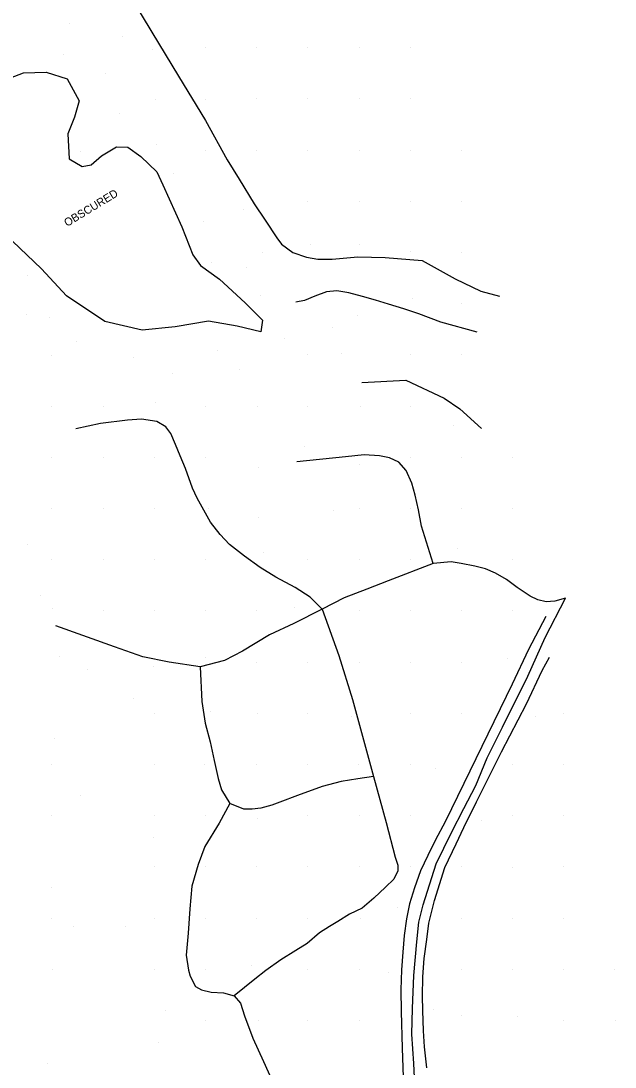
# Model space of a CAD drawing. Extents: x 524772 to 528246, y 273285 to 283088.
# Drawn here: x 527849.8 to 527963, y 274321.4 to 274520.7 of the extents above; entities that cross this region are included whole.
import ezdxf

# ---------------------------------------------------------------- set-up
doc = ezdxf.new("R2010")
doc.units = 0
for name, color, linetype in [('PH Exist DTM Breakline', 7, 'Continuous'), ('PH Exist DTM Obscure Area', 7, 'Continuous'), ('PH Exist DTM Obscure Area Text', 7, 'Continuous'), ('PH Exist DTM Point', 7, 'Continuous')]:
    doc.layers.add(name, color=color, linetype=linetype)

msp = doc.modelspace()

# ---------------------------------------------------------------- linework, layer by layer
at = {"layer": 'PH Exist DTM Breakline'}
for points in [[(527866.42, 274533.52), (527867.96, 274529.7), (527870.63, 274525.31), (527874.74, 274518.54), (527879.81, 274510.15), (527884.93, 274501.67), (527889.06, 274494.22), (527891.36, 274490.53), (527894.19, 274485.84), (527896.28, 274482.72), (527898.51, 274479.34), (527899.44, 274478.1), (527901.55, 274476.56), (527904.17, 274475.63), (527906.35, 274475.26), (527909.05, 274475.26), (527913.94, 274475.69), (527919.19, 274475.61), (527926.24, 274475.02), (527932.52, 274471.5), (527937.39, 274469.18), (527940.93, 274468.23)], [(527936.68, 274461.4), (527929.79, 274463.25), (527925.57, 274464.83), (527922.73, 274465.82), (527919.84, 274466.71), (527917.33, 274467.47), (527914.85, 274468.15), (527912.22, 274468.84), (527909.97, 274469.26), (527907.98, 274469.08), (527905.8, 274468.25), (527903.79, 274467.43), (527902.16, 274467.06)], [(527914.74, 274451.79), (527923.13, 274452.23), (527930.4, 274448.79), (527933.41, 274446.76), (527937.55, 274443.01)], [(527907.18, 274408.58), (527904.86, 274410.9), (527902.03, 274412.71), (527898.36, 274414.72), (527895.38, 274416.55), (527892.39, 274418.7), (527889.52, 274420.9), (527887.73, 274422.82), (527885.89, 274425.18), (527883.37, 274429.73), (527882.47, 274431.65), (527881.1, 274435.38), (527880.11, 274437.84), (527879.25, 274439.97), (527878.31, 274442.05), (527877.4, 274443.36), (527875.64, 274444.33), (527872.75, 274444.77), (527870.05, 274444.62), (527864.96, 274443.97), (527860.26, 274442.94)], [(527953.56, 274410.73), (527951.48, 274410.13), (527949.87, 274410.02), (527948.24, 274410.38), (527946.8, 274411.08), (527944.31, 274412.76), (527942.32, 274414.24), (527940.2, 274415.45), (527938.29, 274416.26), (527936.26, 274416.81), (527933.63, 274417.32), (527931.72, 274417.62), (527928.32, 274417.29), (527927.38, 274420.35), (527926.12, 274424.4), (527925.53, 274427.5), (527924.89, 274430.3), (527924.27, 274432.6), (527923.17, 274435.01), (527921.78, 274436.6), (527920, 274437.43), (527918.09, 274437.78), (527915.18, 274438.02), (527911.64, 274437.65), (527902.35, 274436.69)], [(527928.32, 274417.29), (527919.75, 274414.02), (527915.65, 274412.4), (527911.39, 274410.75), (527907.18, 274408.58), (527901.78, 274405.87), (527897.16, 274403.69), (527891.97, 274400.58), (527888.57, 274398.83), (527883.91, 274397.63), (527878.01, 274398.52), (527873.02, 274399.54), (527867.63, 274401.41), (527856.42, 274405.44)], [(527927.25, 274297.18), (527926.29, 274302.85), (527925.36, 274310.41), (527924.96, 274315.41), (527924.61, 274322.08), (527924.26, 274327.66), (527924.37, 274332.53), (527924.62, 274338.8), (527925.19, 274345.24), (527925.6, 274349.01), (527926.4, 274352.31), (527928.88, 274360.09), (527931.82, 274366.05), (527934.16, 274370.63), (527936.44, 274375.02), (527938.64, 274380.3), (527941.55, 274386.14), (527946.38, 274395.87), (527949.68, 274403.18), (527953.56, 274410.73)], [(527907.18, 274408.58), (527910.35, 274399.78), (527912.95, 274391.37), (527916.95, 274376.73), (527913.94, 274376.27), (527910.77, 274375.77), (527907.18, 274374.82), (527902.46, 274373.1), (527899.12, 274371.84), (527897.58, 274371.27), (527895.49, 274370.69), (527893.82, 274370.5), (527892.22, 274370.48), (527889.59, 274371.58)], [(527949.8, 274407.2), (527946.51, 274400.93), (527943.36, 274394.33), (527930.65, 274368.25), (527928.73, 274364.52), (527927.31, 274361.68), (527925.91, 274358.75), (527924.74, 274355.49), (527923.84, 274352.48), (527923.24, 274349.61), (527922.8, 274346.43), (527922.51, 274343.27), (527922.27, 274339.87), (527922.18, 274336.1), (527922.24, 274331.94), (527922.39, 274325), (527922.64, 274317.63), (527923.04, 274313.7), (527923.12, 274310.68), (527923.31, 274307.7), (527923.66, 274305), (527924.33, 274301.73), (527924.75, 274299.14), (527925.3, 274296.8)], [(527927.09, 274321.26), (527926.68, 274325.24), (527926.47, 274328.28), (527926.37, 274332.16), (527926.3, 274334.87), (527926.33, 274338.59), (527926.63, 274342.06), (527927.09, 274345.67), (527927.52, 274348.76), (527928.6, 274353.1), (527930.55, 274359.39), (527932.7, 274363.9), (527934.15, 274367.03), (527936.56, 274371.89), (527938.81, 274376.33), (527941.34, 274381.41), (527946.13, 274390.55), (527949.11, 274396.95), (527950.49, 274399.44)], [(527883.91, 274397.63), (527884.24, 274391.04), (527884.89, 274386.86), (527885.81, 274383.31), (527886.57, 274379.75), (527887.36, 274376.36), (527888.02, 274374.21), (527889.59, 274371.58), (527887.55, 274367.84), (527884.84, 274363.37), (527883.52, 274359.94), (527882.34, 274355.86), (527881.96, 274351.51), (527881.61, 274346.88), (527881.24, 274342.71), (527881.67, 274339.81), (527882.01, 274338.69), (527883.01, 274336.7), (527884.18, 274336.08), (527886.01, 274335.67), (527888.35, 274335.51), (527890.41, 274334.97), (527891.59, 274333.58), (527892.4, 274331.15), (527893.98, 274326.87), (527896.02, 274322.44), (527897.44, 274319.19)], [(527916.95, 274376.73), (527919.38, 274367.94), (527921.09, 274361.35), (527921.56, 274359.84), (527921.58, 274358.77), (527920.84, 274357.17), (527919.22, 274355.63), (527917.03, 274353.54), (527914.77, 274351.67), (527912.39, 274350.48), (527910.18, 274349.11), (527908.58, 274348.18), (527906.66, 274346.94), (527904.34, 274344.9), (527902.18, 274343.58), (527899.32, 274341.81), (527896.46, 274339.79), (527894.35, 274338.15), (527890.41, 274334.97)]]:
    msp.add_lwpolyline(points, dxfattribs=at)
at = {"layer": 'PH Exist DTM Obscure Area'}
for points in [[(527844.92, 274508.75), (527850.23, 274510.76), (527854.56, 274510.87), (527858.56, 274509.6), (527860.88, 274505.42), (527859.99, 274502.34), (527858.73, 274499.16), (527858.97, 274494.38), (527861.41, 274492.91), (527863.17, 274493.25), (527865.11, 274494.94), (527868, 274496.66), (527870.11, 274496.62), (527872.64, 274494.84), (527875.66, 274491.91), (527876.78, 274489.41)], [(527876.78, 274489.41), (527880.45, 274481.43), (527882.53, 274476.13), (527884.01, 274474.06), (527887.59, 274471.45), (527892.5, 274466.98), (527895.8, 274463.65), (527895.46, 274461.45), (527890.97, 274462.5), (527885.53, 274463.44), (527879.13, 274462.41), (527872.87, 274461.74), (527865.77, 274463.41), (527858.48, 274468.26), (527853.69, 274473.42), (527848.15, 274478.69)]]:
    msp.add_lwpolyline(points, dxfattribs=at)
at = {"layer": 'PH Exist DTM Point'}
for p, q in [((527859, 274520.18), (527859, 274520.18)), ((527869.07, 274517.69), (527869.07, 274517.69)), ((527874.77, 274515.15), (527874.77, 274515.15)), ((527884.93, 274515.57), (527884.93, 274515.57)), ((527894.71, 274515.56), (527894.71, 274515.56)), ((527904.46, 274515.56), (527904.46, 274515.56)), ((527914.2, 274515.53), (527914.2, 274515.53)), ((527923.97, 274515.56), (527923.97, 274515.56)), ((527857.87, 274514.24), (527857.87, 274514.24)), ((527865.95, 274510.71), (527865.95, 274510.71)), ((527875.33, 274505.76), (527875.33, 274505.76)), ((527885.02, 274505.78), (527885.02, 274505.78)), ((527894.71, 274505.8), (527894.71, 274505.8)), ((527904.46, 274505.8), (527904.46, 274505.8)), ((527914.19, 274505.81), (527914.19, 274505.81)), ((527923.97, 274505.8), (527923.97, 274505.8)), ((527868.56, 274503.05), (527868.56, 274503.05)), ((527875.63, 274497.06), (527875.63, 274497.06)), ((527861.15, 274495.79), (527861.15, 274495.79)), ((527884.87, 274496.06), (527884.87, 274496.06)), ((527894.71, 274496.05), (527894.71, 274496.05)), ((527904.44, 274496.06), (527904.44, 274496.06)), ((527914.22, 274496.05), (527914.22, 274496.05)), ((527923.97, 274496.05), (527923.97, 274496.05)), ((527933.74, 274496.05), (527933.74, 274496.05)), ((527878.8, 274491.57), (527878.8, 274491.57)), ((527904.46, 274486.29), (527904.46, 274486.29)), ((527914.22, 274486.29), (527914.22, 274486.29)), ((527923.97, 274486.29), (527923.97, 274486.29)), ((527933.72, 274486.29), (527933.72, 274486.29)), ((527892.26, 274484.64), (527892.26, 274484.64)), ((527884.48, 274482.46), (527884.48, 274482.46)), ((527904.95, 274478.13), (527904.95, 274478.13)), ((527914.36, 274478.08), (527914.36, 274478.08)), ((527895.87, 274476.51), (527895.87, 274476.51)), ((527924.08, 274476.65), (527924.08, 274476.65)), ((527933.72, 274476.54), (527933.72, 274476.54)), ((527886.04, 274474.6), (527886.04, 274474.6)), ((527892.69, 274473.76), (527892.69, 274473.76)), ((527851.05, 274472.09), (527851.05, 274472.09)), ((527895.43, 274468.3), (527895.43, 274468.3)), ((527924.43, 274467.79), (527924.43, 274467.79)), ((527933.72, 274466.79), (527933.72, 274466.79)), ((527850.77, 274464.74), (527850.77, 274464.74)), ((527855.15, 274464.23), (527855.15, 274464.23)), ((527913.85, 274464.61), (527913.85, 274464.61)), ((527909.08, 274462.24), (527909.08, 274462.24)), ((527860.43, 274459.53), (527860.43, 274459.53)), ((527900.01, 274460.18), (527900.01, 274460.18)), ((527887.2, 274457.88), (527887.2, 274457.88)), ((527910.84, 274457.21), (527910.84, 274457.21)), ((527855.69, 274456.99), (527855.69, 274456.99)), ((527871.29, 274456.63), (527871.29, 274456.63)), ((527904.46, 274457.03), (527904.46, 274457.03)), ((527923.97, 274457.03), (527923.97, 274457.03)), ((527933.72, 274457.03), (527933.72, 274457.03)), ((527878.74, 274453.4), (527878.74, 274453.4)), ((527891.47, 274454.33), (527891.47, 274454.33)), ((527855.69, 274447.28), (527855.69, 274447.28)), ((527865.46, 274447.3), (527865.46, 274447.3)), ((527875.45, 274448.04), (527875.45, 274448.04)), ((527884.95, 274447.28), (527884.95, 274447.28)), ((527894.94, 274447.25), (527894.94, 274447.25)), ((527904.46, 274447.28), (527904.46, 274447.28)), ((527923.97, 274447.28), (527923.97, 274447.28)), ((527914.48, 274447.2), (527914.48, 274447.2)), ((527932.11, 274443.61), (527932.11, 274443.61)), ((527903.78, 274439.63), (527903.78, 274439.63)), ((527855.69, 274437.54), (527855.69, 274437.54)), ((527865.43, 274437.5), (527865.43, 274437.5)), ((527875.2, 274437.53), (527875.2, 274437.53)), ((527884.95, 274437.53), (527884.95, 274437.53)), ((527923.97, 274437.53), (527923.97, 274437.53)), ((527933.72, 274437.53), (527933.72, 274437.53)), ((527943.48, 274437.53), (527943.48, 274437.53)), ((527894.99, 274435.57), (527894.99, 274435.57)), ((527914.21, 274436.19), (527914.21, 274436.19)), ((527855.69, 274427.77), (527855.69, 274427.77)), ((527865.45, 274427.77), (527865.45, 274427.77)), ((527875.2, 274427.77), (527875.2, 274427.77)), ((527885.57, 274427.87), (527885.57, 274427.87)), ((527909.39, 274427.39), (527909.39, 274427.39)), ((527914.22, 274427.77), (527914.22, 274427.77)), ((527923.97, 274427.77), (527923.97, 274427.77)), ((527933.72, 274427.77), (527933.72, 274427.77)), ((527943.48, 274427.77), (527943.48, 274427.77)), ((527895.13, 274426.02), (527895.13, 274426.02)), ((527851.04, 274420.84), (527851.04, 274420.84)), ((527895.98, 274419.43), (527895.98, 274419.43)), ((527932.99, 274420.15), (527932.99, 274420.15)), ((527855.69, 274418.02), (527855.69, 274418.02)), ((527865.45, 274418.02), (527865.45, 274418.02)), ((527875.2, 274418.02), (527875.2, 274418.02)), ((527884.95, 274418.02), (527884.95, 274418.02)), ((527904.46, 274418.02), (527904.46, 274418.02)), ((527914.22, 274418.02), (527914.22, 274418.02)), ((527923.97, 274418.02), (527923.97, 274418.02)), ((527943.48, 274418.02), (527943.48, 274418.02)), ((527853.47, 274411.26), (527853.47, 274411.26)), ((527855.85, 274408.79), (527855.85, 274408.79)), ((527865.45, 274408.27), (527865.45, 274408.27)), ((527875.2, 274408.27), (527875.2, 274408.27)), ((527884.95, 274408.27), (527884.95, 274408.27)), ((527894.71, 274408.27), (527894.71, 274408.27)), ((527901.89, 274408.88), (527901.89, 274408.88)), ((527914.22, 274408.27), (527914.22, 274408.27)), ((527923.97, 274408.27), (527923.97, 274408.27)), ((527933.72, 274408.27), (527933.72, 274408.27)), ((527943.48, 274408.27), (527943.48, 274408.27)), ((527857.06, 274399.53), (527857.06, 274399.53)), ((527884.91, 274399.45), (527884.91, 274399.45)), ((527875.08, 274397.73), (527875.08, 274397.73)), ((527894.71, 274398.51), (527894.71, 274398.51)), ((527904.46, 274398.51), (527904.46, 274398.51)), ((527914.22, 274398.51), (527914.22, 274398.51)), ((527923.97, 274398.51), (527923.97, 274398.51)), ((527933.72, 274398.51), (527933.72, 274398.51)), ((527942.45, 274399.14), (527942.45, 274399.14)), ((527862.36, 274397.18), (527862.36, 274397.18)), ((527871.2, 274391.54), (527871.2, 274391.54)), ((527875.2, 274388.76), (527875.2, 274388.76)), ((527885.98, 274389.05), (527885.98, 274389.05)), ((527894.88, 274388.71), (527894.88, 274388.71)), ((527904.46, 274388.76), (527904.46, 274388.76)), ((527912.69, 274388.24), (527912.69, 274388.24)), ((527923.97, 274388.76), (527923.97, 274388.76)), ((527933.72, 274388.76), (527933.72, 274388.76)), ((527947.81, 274388.08), (527947.81, 274388.08)), ((527953.23, 274388.76), (527953.23, 274388.76)), ((527856.17, 274384.01), (527856.17, 274384.01)), ((527855.69, 274379), (527855.69, 274379)), ((527875.2, 274379), (527875.2, 274379)), ((527884.7, 274379.05), (527884.7, 274379.05)), ((527894.71, 274379), (527894.71, 274379)), ((527904.46, 274379), (527904.46, 274379)), ((527914.15, 274379.01), (527914.15, 274379.01)), ((527923.98, 274379.03), (527923.98, 274379.03)), ((527928.85, 274378.33), (527928.85, 274378.33)), ((527943.48, 274379), (527943.48, 274379)), ((527953.23, 274379), (527953.23, 274379)), ((527861.04, 274373.16), (527861.04, 274373.16)), ((527855.69, 274369.25), (527855.69, 274369.25)), ((527875.2, 274369.25), (527875.2, 274369.25)), ((527884.95, 274369.25), (527884.95, 274369.25)), ((527894.85, 274368.77), (527894.85, 274368.77)), ((527904.46, 274369.25), (527904.46, 274369.25)), ((527914.22, 274369.25), (527914.22, 274369.25)), ((527923.93, 274369.24), (527923.93, 274369.24)), ((527937.49, 274368.28), (527937.49, 274368.28)), ((527943.49, 274369.27), (527943.49, 274369.27)), ((527953.23, 274369.25), (527953.23, 274369.25)), ((527875.09, 274365.12), (527875.09, 274365.12)), ((527875.2, 274359.5), (527875.2, 274359.5)), ((527884.95, 274359.5), (527884.95, 274359.5)), ((527894.71, 274359.5), (527894.71, 274359.5)), ((527904.46, 274359.5), (527904.46, 274359.5)), ((527914.22, 274359.5), (527914.22, 274359.5)), ((527923.97, 274359.5), (527923.97, 274359.5)), ((527933.72, 274359.5), (527933.72, 274359.5)), ((527943.5, 274359.48), (527943.5, 274359.48)), ((527953.23, 274359.5), (527953.23, 274359.5)), ((527855.6, 274355.62), (527855.6, 274355.62)), ((527921.51, 274351.86), (527921.51, 274351.86)), ((527855.68, 274349.74), (527855.68, 274349.74)), ((527875.2, 274349.74), (527875.2, 274349.74)), ((527884.97, 274349.75), (527884.97, 274349.75)), ((527894.71, 274349.74), (527894.71, 274349.74)), ((527904.46, 274349.74), (527904.46, 274349.74)), ((527914.4, 274349.67), (527914.4, 274349.67)), ((527933.7, 274349.76), (527933.7, 274349.76)), ((527943.45, 274349.76), (527943.45, 274349.76)), ((527953.23, 274349.74), (527953.23, 274349.74)), ((527859.81, 274348.1), (527859.81, 274348.1)), ((527869.71, 274348.12), (527869.71, 274348.12)), ((527855.71, 274340.01), (527855.71, 274340.01)), ((527875.2, 274339.99), (527875.2, 274339.99)), ((527884.95, 274339.99), (527884.95, 274339.99)), ((527893.64, 274340.67), (527893.64, 274340.67)), ((527904.46, 274339.99), (527904.46, 274339.99)), ((527914.22, 274339.99), (527914.22, 274339.99)), ((527933.75, 274339.98), (527933.75, 274339.98)), ((527943.48, 274339.99), (527943.48, 274339.99)), ((527953.23, 274339.99), (527953.23, 274339.99)), ((527962.96, 274340), (527962.96, 274340)), ((527919.9, 274339.41), (527919.9, 274339.41)), ((527877.27, 274332.24), (527877.27, 274332.24)), ((527928.33, 274332.26), (527928.33, 274332.26)), ((527884.95, 274330.24), (527884.95, 274330.24)), ((527894.95, 274330.23), (527894.95, 274330.23)), ((527904.46, 274330.24), (527904.46, 274330.24)), ((527914.22, 274330.24), (527914.22, 274330.24)), ((527933.72, 274331.16), (527933.72, 274331.16)), ((527944.31, 274331.06), (527944.31, 274331.06)), ((527953.23, 274330.24), (527953.23, 274330.24)), ((527962.98, 274330.24), (527962.98, 274330.24)), ((527876.02, 274326.03), (527876.02, 274326.03)), ((527854.8, 274322.11), (527854.8, 274322.11))]:
    msp.add_line(p, q, dxfattribs=at)

# ---------------------------------------------------------------- texts
at = {"layer": 'PH Exist DTM Obscure Area Text'}
msp.add_text('OBSCURED', height=1.524, rotation=31.339, dxfattribs=at).set_placement((527858.57, 274481.4))

doc.saveas('drawing.dxf')
